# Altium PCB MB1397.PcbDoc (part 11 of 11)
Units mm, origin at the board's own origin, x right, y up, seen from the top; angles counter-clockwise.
Board outline 118.24 x 172.86 mm, 6 copper layers (Top Layer, L2_GND, L3_VCC, L4_SIG, L5_GND, Bottom Layer), stack 1.631 mm thick; 819 components, 632 nets, 2875 pads, 1523 vias.
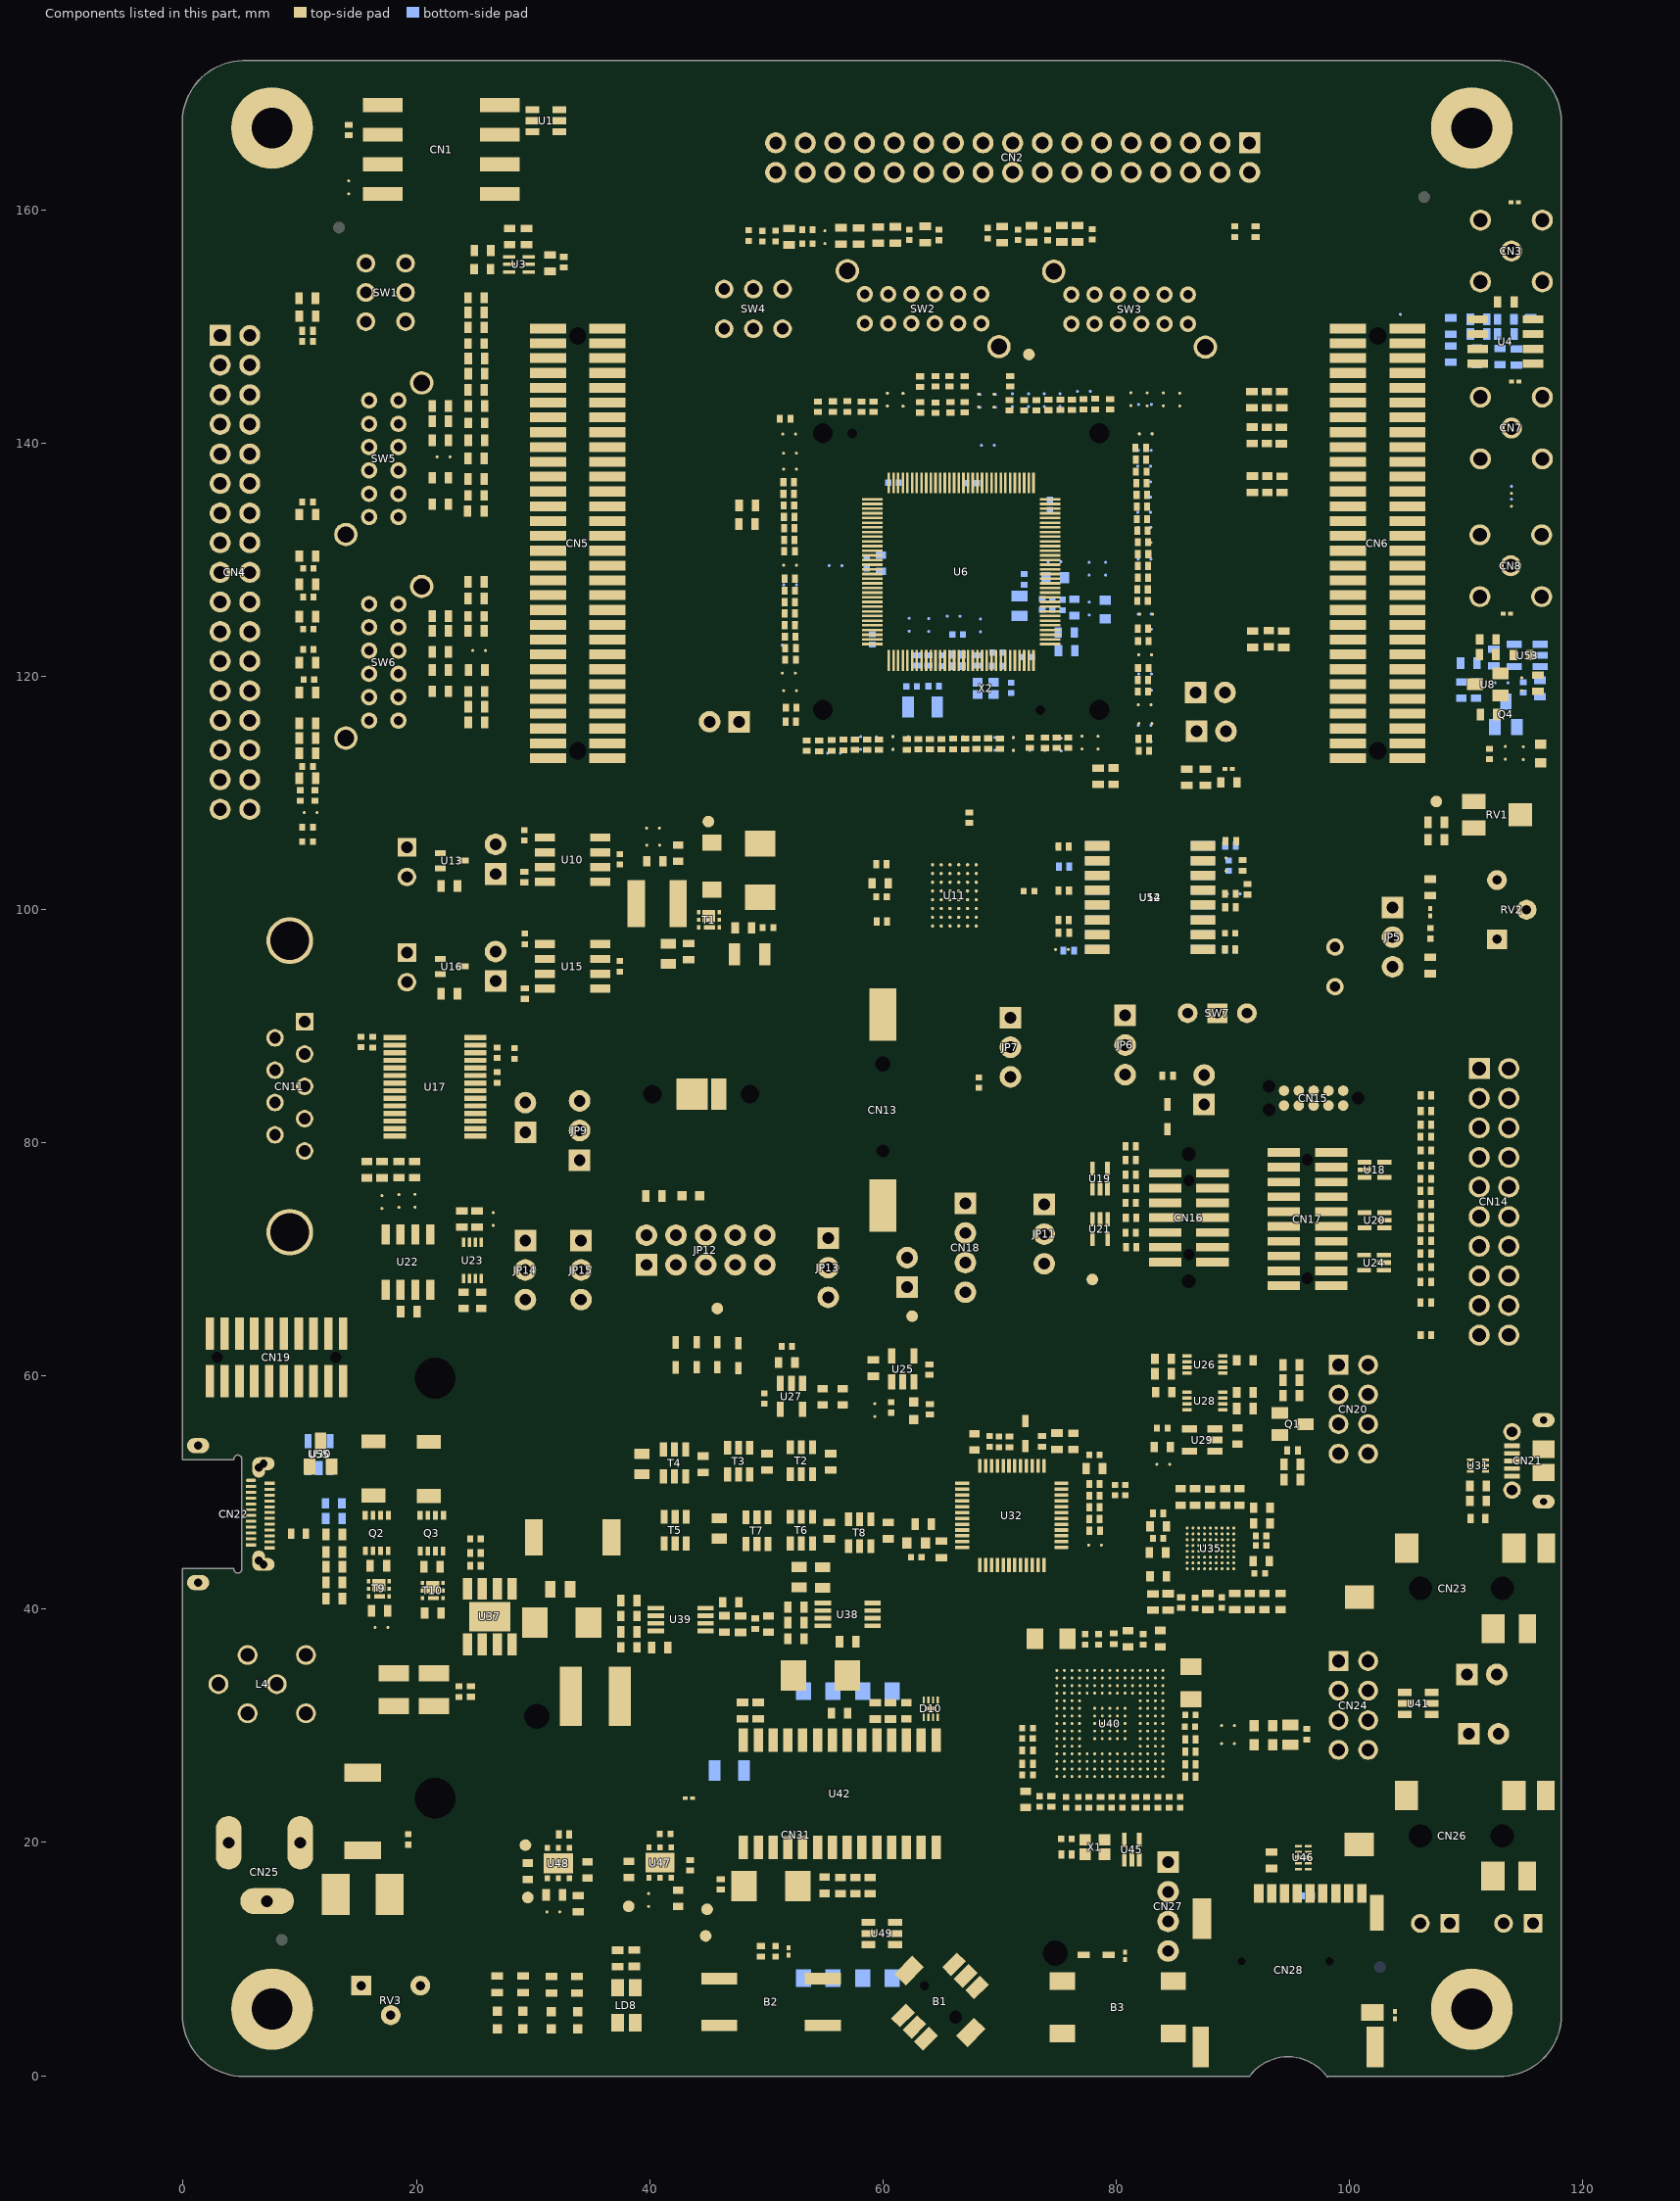
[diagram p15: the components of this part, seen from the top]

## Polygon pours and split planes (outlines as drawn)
no net on Top Overlay (solid): 103.025,168.605 ccw(c102.567,168.605) 102.567,169.063 ccw(c102.567,168.605) 102.109,168.605 ccw(c102.567,168.605) 102.567,168.147 ccw(c102.567,168.605) 103.025,168.605
no net on Top Overlay (solid): 102.707,164.287 ccw(c102.059,164.287) 102.059,164.935 ccw(c102.059,164.287) 101.411,164.287 ccw(c102.059,164.287) 102.059,163.64 ccw(c102.059,164.287) 102.707,164.287
no net on Top Overlay (solid): 99.392,168.605 99.392,169.24 99.646,169.24 99.646,168.605 99.392,168.605
no net on Top Overlay (solid): 100.154,167.208 100.154,166.7 101.678,166.7 101.678,167.208 100.154,167.208
no net on Top Overlay (solid): 99.519,163.716 99.773,163.716 99.773,164.16 99.519,164.16 99.519,163.716
no net on Top Overlay (solid): 103.025,168.605 ccw(c102.567,168.605) 102.567,169.063 ccw(c102.567,168.605) 102.109,168.605 ccw(c102.567,168.605) 102.567,168.147 ccw(c102.567,168.605) 103.025,168.605
no net on Top Overlay (solid): 102.707,164.287 ccw(c102.059,164.287) 102.059,164.935 ccw(c102.059,164.287) 101.411,164.287 ccw(c102.059,164.287) 102.059,163.64 ccw(c102.059,164.287) 102.707,164.287
no net on Top Overlay (solid): 99.392,168.605 99.392,169.24 99.646,169.24 99.646,168.605 99.392,168.605
no net on Top Overlay (solid): 100.154,167.208 100.154,166.7 101.678,166.7 101.678,167.208 100.154,167.208
no net on Top Overlay (solid): 99.519,163.716 99.773,163.716 99.773,164.16 99.519,164.16 99.519,163.716
no net on Top Overlay (solid): 457 vertices, not listed, extent 69.214,77.689 75.841,83.176
no net on Top Overlay (solid): 227 vertices, not listed, extent 72.022,78.87 74.874,81.995
no net on Top Overlay (solid): 457 vertices, not listed, extent 69.214,77.689 75.841,83.176
no net on Top Overlay (solid): 227 vertices, not listed, extent 72.022,78.87 74.874,81.995
GND on Top Layer "L4_SIG-No Net" (solid, pour order 261): 25 vertices, not listed, extent 23.467,36.703 32.004,49.2
GND_EXT_UNFILT on Top Layer "TOP-GND_EXT_UNFILT" (solid, pour order 215): 17 vertices, not listed, extent 8.862,20.368 19.756,32.433
NetLD5_2 on Top Layer "L4_SIG-No Net" (solid, pour order 256): 38.875,89.637 38.215,88.976 38.215,79.591 39.04,78.765 44.348,78.765 44.968,79.385 44.968,89.118 44.45,89.637
AGND on Top Layer "L4_SIG-No Net" (solid, pour order 264): 79.395,111.115 81.923,111.115 82.166,110.871 82.166,109.774 81.945,109.553 79.582,109.553 79.231,109.904 79.231,110.92 79.334,111.023
5V_USB_CHGR on Top Layer "TOP-5V_USB_CHGR" (solid, pour order 226): 26 vertices, not listed, extent 46.835,60.627 61.44,65.453
NetC63_2 on Top Layer "TOP-NETC77_1" (solid, pour order 232): 17 vertices, not listed, extent 41.374,58.989 51.534,63.421
5V_USB_PD on Top Layer "TOP-5V_USB_PD" (solid, pour order 219): 32.865,64.437 42.771,64.437 43.025,64.183 43.025,62.278 42.771,62.024 33.119,62.024 23.868,52.774 14.709,52.774 14.315,53.167 14.315,55.166 14.732,55.583 24.011,55.583 32.865,64.437
GND on Top Layer "TOP-GND 1" (solid, pour order 212): 52.036,59.492 51.915,59.613 51.915,60.582 51.915,61.727 51.915,62.128 51.915,62.944 51.915,63.167 52.169,63.421 53.312,63.421 53.566,63.167 53.566,60.819
NetC71_2 on Top Layer "Top Layer-NetC71_2" (solid, pour order 208): 21 vertices, not listed, extent 49,56.055 51.599,57.905
3V3_STLK on Top Layer "TOP-3V3_STLK" (solid, pour order 224): 17 vertices, not listed, extent 52.296,55.928 57.757,57.96
5V on Top Layer "TOP-5V 2" (solid, pour order 230): 618 vertices, not listed, extent 37.818,71.041 51.534,76.883
5V on Top Layer "TOP-5V 1" (solid, pour order 229): 53 vertices, not listed, extent 41.563,15.542 44.676,17.955
SH1_D on Top Layer "TOP-SH1_D" (solid, pour order 202): 25 vertices, not listed, extent 44.93,47.292 47.978,55.166
NetC151_2 on Top Layer "TOP-NETC34_2" (solid, pour order 209): 95 vertices, not listed, extent 27.912,13.129 31.468,17.32
NetC149_2 on Top Layer "TOP-NETC29_2" (solid, pour order 210): 156 vertices, not listed, extent 37.183,15.542 41.247,17.32
AMP_VDD on Top Layer "TOP-AMP_VDD" (solid, pour order 217): 30 vertices, not listed, extent 39.723,39.926 46.708,49.07
AMP_5V on Top Layer "TOP-AMP_5V" (solid, pour order 218): 18 vertices, not listed, extent 56.106,44.066 58.392,48.892
VIN_EXT_UNFILT on Top Layer "TOP-VIN_EXT_UNFILT" (solid, pour order 220): 28 vertices, not listed, extent 2.639,11.834 20.292,32.56
VIN_EXT_CONN on Top Layer "TOP-VIN_EXT_CONN" (solid, pour order 221): 17 vertices, not listed, extent 7.719,11.478 14.958,23.035
1V8_LDO on Top Layer "TOP-1V8_LDO" (solid, pour order 222): 89 vertices, not listed, extent 84.3,51.737 87.221,54.912
1V8 on Top Layer "TOP-1V8" (solid, pour order 223): 64 vertices, not listed, extent 82.141,50.34 83.919,53.134
5V_USB_CHGR on Top Layer "TOP-5V_USB_CHGR 1" (solid, pour order 227): 22 vertices, not listed, extent 111.224,46.784 112.875,51.483
VIN_EXT on Top Layer "TOP-VIN_EXT" (solid, pour order 235): 35 vertices, not listed, extent 4.036,33.195 26.132,39.164
GND on Top Layer "TOP-GND" (solid, pour order 211): 21 vertices, not listed, extent 47.662,94.104 51.661,102.791
3V3 on Top Layer "TOP-3V3" (solid, pour order 225): 77 vertices, not listed, extent 36.802,12.748 41.374,15.669
5V on Top Layer "TOP-5V" (solid, pour order 228): 48 vertices, not listed, extent 1.115,97.965 36.548,103.045
GND on Top Layer "TOP-GND 3" (solid, pour order 214): 15.847,29.258 15.466,29.639 15.466,32.052 15.847,32.433 16.655,32.433 19.51,32.433 20.511,32.433 22.939,32.433 23.32,32.814 24.077,32.814 24.892,32.814 25.654,32.814 25.654,30.81 24.102,29.258
GND on Top Layer "TOP-GND 2" (solid, pour order 213): 19 vertices, not listed, extent 16.863,39.291 19.022,41.247
SH0_D on Top Layer "TOP-SH0_D" (solid, pour order 203): 21 vertices, not listed, extent 38.326,50.086 42.517,54.912
T50_6 on Top Layer "TOP-T50_6" (solid, pour order 200): 49 vertices, not listed, extent 44.93,40.307 56.106,49.197
SH2_D on Top Layer "TOP-SH2_D" (solid, pour order 201): 22 vertices, not listed, extent 51.026,43.228 53.947,49.197
NetL5_1 on Top Layer "L4_SIG-No Net" (solid, pour order 260): 17 vertices, not listed, extent 26.67,29.134 34.722,35.692
CAL_D on Top Layer "TOP-CAL_D" (solid, pour order 216): 65 vertices, not listed, extent 48.232,46.657 54.709,55.547
NetR249_1 on Top Layer "TOP-NETR324_1" (solid, pour order 204): 23 vertices, not listed, extent 19.784,41.406 22.959,44.123
NetR246_1 on Top Layer "TOP-NETR318_1" (solid, remove dead copper, pour order 205): 23 vertices, not listed, extent 13.307,39.799 17.922,45.514
NetC41_1 on Top Layer "TOP-NETC22_2" (solid, pour order 231): 40.993,103.172 40.739,103.426 40.739,103.576 41.59,103.576 41.59,104.696 43.406,104.696 43.787,105.077 43.787,107.744 44.676,108.633 51.153,108.633 51.415,108.372 51.415,104.235 51.114,103.934 44.422,103.934 43.66,103.172
NetD1_1 on Top Layer "Top Layer-NetD1_1" (solid, pour order 233): 41.501,97.965 41.247,98.219 41.247,102.791 43.818,102.791 43.945,102.918 46.454,102.918 46.611,102.762 46.611,99.519 46.611,99.265 46.2,98.854 43.914,98.854 43.66,98.6 43.66,98.219 43.406,97.965
NetR172_1 on Top Layer "TOP-NETR48_1" (solid, pour order 234): 30 vertices, not listed, extent 44.676,94.513 48.232,99.362
VBUS on Top Layer "TOP-VBUS" (solid, remove dead copper, pour order 199): 32 vertices, not listed, extent 10.97,39.418 18.26,50.975
NetQ2_1 on Top Layer "TOP-NETQ2_1 1" (solid, pour order 207): 14.958,43.101 14.755,43.304 14.755,45.184 14.958,45.387 17.117,45.387 17.117,44.625 16.961,44.469 15.591,44.457 15.591,43.101
NetQ2_1 on Top Layer "TOP-NETQ2_1" (solid, pour order 206): 18.982,44.069 18.885,44.166 18.885,45.263 19.012,45.39 21.806,45.39 21.806,44.628 21.679,44.501 21.328,44.501 19.743,44.501 19.312,44.069
5V_EXT on Top Layer "L4_SIG-No Net" (solid, pour order 262): 40 vertices, not listed, extent 19.276,29.261 39.219,54.509
NetLD5_2 on Bottom Layer "Bottom Layer-NetLD5_2" (solid, pour order 257): 38.875,89.637 44.45,89.637 44.968,89.118 44.968,79.385 44.348,78.765 39.04,78.765 38.215,79.591 38.215,88.964 38.532,89.281
VDD on Bottom Layer "BOTTOM-VDD" (solid, pour order 236): 149 vertices, not listed, extent 83.03,60.754 106.906,64.564
VDD1 on Bottom Layer "BOTTOM-VDD1" (solid, pour order 237): 136 vertices, not listed, extent 62.329,42.466 74.775,53.642
NetQ2_1 on Bottom Layer "BOTTOM-NETQ2_1" (solid, pour order 238): 19.657,45.26 19.657,44.244 19.53,44.117 16.482,44.117 16.101,43.736 16.101,43.228 15.974,43.101 14.958,43.101 14.755,43.304 14.755,45.184 14.958,45.387 19.53,45.387 19.657,45.26
GND_EXT_UNFILT on Bottom Layer "BOTTOM-GND_EXT_UNFILT" (solid, pour order 239): 26 vertices, not listed, extent 0.734,13.002 17.879,32.433
AGND on L4_SIG "L4_SIG-No Net" (solid, pour order 265): 21 vertices, not listed, extent 76.022,109.964 82.549,123.977
VDD1 on L4_SIG "L4_SIG-VDD1" (solid, pour order 240): 185 vertices, not listed, extent 51.407,41.323 66.012,67.739
3V3 on L4_SIG "L4_SIG-3V3" (solid, pour order 243): 442 vertices, not listed, extent 36.675,8.303 97.254,17.447
5V_EXT on L4_SIG "L4_SIG-No Net" (solid, pour order 263): 30.071,52.603 33.779,52.603 48.74,67.564 48.74,70.423 48.28,70.884 46.419,70.884 46.025,70.49 46.025,68.044 32.593,54.612 29.545,54.612 29.21,54.277 29.21,52.924 29.531,52.603 29.591,52.59
VIN_EXT_CONN on L4_SIG "L4_SIG-VIN_EXT_CONN" (solid, pour order 242): 14.78,11.478 10.792,11.478 10.361,11.91 10.361,15.847 7.719,18.489 7.719,22.019 8.735,23.035 10.386,23.035 12.545,20.876 12.545,18.336 13.18,17.701 14.704,17.701 14.958,17.447 14.958,11.656 14.78,11.478
VIN_EXT_UNFILT on L4_SIG "L4_SIG-VIN_EXT_UNFILT" (solid, pour order 241): 23 vertices, not listed, extent 2.639,11.834 20.292,32.56
VIN_EXT on L4_SIG "L4_SIG-VIN_EXT" (solid, pour order 244): 32 vertices, not listed, extent 4.036,33.195 23.391,39.164
1V8 on L4_SIG "L4_SIG-No Net" (solid, pour order 255): 19 vertices, not listed, extent 82.296,40.856 93.525,53.008
5V on L3_VCC "L3_VCC-5V 1" (solid, remove dead copper, pour order 253): 72 vertices, not listed, extent 0.445,100.633 117.666,172.274
VBUS on L3_VCC "L3_VCC-VBUS" (solid, remove dead copper, pour order 248): 0.445,39.419 0.445,65.913 11.227,65.913 13.435,63.705 13.435,40.031 12.822,39.419
5V on L3_VCC "L3_VCC-5V" (solid, remove dead copper, pour order 252): 42 vertices, not listed, extent 33.501,8.431 92.429,114.095
VDD on L3_VCC "L3_VCC-VDD" (solid, remove dead copper, pour order 246): 58 vertices, not listed, extent 42.645,27.735 94.207,78.535
3V3_STLK on L3_VCC "L3_VCC-3V3_STLK" (solid, pour order 249): 22 vertices, not listed, extent 54.583,17.018 86.587,61.009
3V3 on L3_VCC "L3_VCC-3V3" (solid, pour order 250): 48 vertices, not listed, extent 72.871,11.733 103.859,86.663
3V3 on L3_VCC "L3_VCC-3V3" (solid, remove dead copper, pour order 251): 53 vertices, not listed, extent 0.445,0.446 111.479,164.387
VDD on L3_VCC "L3_VCC-VDD" (solid, pour order 245): 117 vertices, not listed, extent 20.801,0.446 117.666,157.275
VDD_MCU on L3_VCC "L3_VCC-VDD_MCU" (solid, remove dead copper, pour order 247): 25 vertices, not listed, extent 52.297,67.867 86.587,138.162
AGND on L2_GND "L2_GND-AGND" (solid, pour order 259): 37 vertices, not listed, extent 76.68,107.076 117.665,161.107
GND_EXT_UNFILT on L2_GND "L2_GND-GND" (solid, remove dead copper, pour order 267): 25 vertices, not listed, extent 0.445,12.967 17.819,32.346
GND on L2_GND "L2_GND-GND" (solid, remove dead copper, pour order 266): 132 vertices, not listed, extent 0.445,0.445 117.666,172.273
no net on Top Solder "L4_SIG-No Net" (solid): 38.875,89.637 44.45,89.637 44.968,89.118 44.968,79.385 44.348,78.765 39.04,78.765 38.215,79.591 38.215,88.976
GND_EXT_UNFILT on L5_GND "L5_GND-GND" (solid, remove dead copper, pour order 268): 23 vertices, not listed, extent 0.444,13.005 17.836,32.346
AGND on L5_GND "L5_GND-AGND" (solid, pour order 254): 108.92,114.475 108.92,135.237 108.097,136.06 108.097,158.852 110.353,161.107 117.665,161.107 117.665,113.713 109.682,113.713 108.92,114.475
GND on L5_GND "L5_GND-GND" (solid, remove dead copper, pour order 269): 99 vertices, not listed, extent 0.452,0.42 117.673,172.249
no net on Bottom Solder "L4_SIG-No Net" (solid): 38.875,89.637 44.45,89.637 44.968,89.118 44.968,79.385 44.348,78.765 39.04,78.765 38.215,79.591 38.215,88.976

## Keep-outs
L2_GND:
  lines w0.254: 90.721,0.056 cw(c94.742,-2.515) 98.779,0.03
L3_VCC:
  lines w0.254: 90.721,0.056 cw(c94.742,-2.515) 98.779,0.03
L5_GND:
  lines w0.254: 90.721,0.056 cw(c94.742,-2.515) 98.779,0.03
Bottom Layer:
  circle w0.025: c54.843,117.106 r2.505
  circle w0.025: c78.563,117.106 r2.505
  circle w0.025: c54.843,140.831 r2.505
Keep-Out Layer:
  lines w0.127: 118.11,5.156 118.11,5.156
Multi-Layer:
  circle w0.025: c57.383,140.826 r0.705
  circle w0.025: c54.843,117.106 r1.105
  circle w0.025: c54.843,140.826 r1.105
  circle w0.025: c78.563,140.826 r1.105
  circle w0.025: c78.563,117.106 r1.105
  circle w0.025: c73.483,117.106 r0.705

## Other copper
Top Layer:
  rectangle net GND: 27.324,38.1 29.25,40.12
  rectangle net NetR249_1: 20.222,41.456 22.614,42.517
  rectangle net NetC63_2: 50.458,59.182 51.317,59.776
  rectangle net NetR246_1: 15.419,41.581 17.922,42.545
  rectangle net NetQ2_1: 19.53,44.501 21.776,45.387
  rectangle net AMP_VDD: 41.011,47.802 41.467,48.943
  rectangle net AMP_VDD: 41.958,45.63 42.364,48.901
  rectangle net SH0_D: 40.505,53.414 42.257,53.911
  rectangle net SH0_D: 40.601,51.151 42.279,51.664
  rectangle net GND: 23.789,38.1 28.789,40.64
  text "1" at 57.462,-24.867 h1.91
  text "1" at 57.462,-24.867 h1.91
  text "PRIMARY SIDE" at 44.762,-28.677 h1.52
  text "PRIMARY SIDE" at 44.762,-28.677 h1.52
Bottom Layer:
  text "6" at 56.192,-24.867 h1.91
  text "6" at 56.192,-24.867 h1.91
  text "SECONDARY SIDE" at 44.762,-28.677 h1.52
Multi-Layer:
  text "FAB DARWING & DRILL LEGEND" at 44.762,-28.677 h1.52

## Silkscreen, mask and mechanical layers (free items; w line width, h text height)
Top Overlay:
  drawing of 2954 lines, arcs and shapes, not listed
  text "EXT I2C" at 21.189,170.942 h0.76
  text "MB1397B" at 92.606,170.231 h0.89
  text "STM32G474E-EVAL" at 71.45,170.155 h1.52
  text "MC1" at 66.761,169.545 h0.76
  text "AIN" at 109.67,159.133 h0.76 r90
  text "MC2" at 4.699,154.912 h0.76
  text "COMP_OUT" at 72.898,149.885 h0.76 r90
  text "PC8" at 26.924,149.482 h0.76
  text "PC7" at 95.377,149.426 h0.76
  text "PC6" at 106.934,149.428 h0.76
  text "PA8" at 38.687,149.352 h0.76
  text "PA11" at 26.924,148.202 h0.76
  text "PD15" at 95.377,148.158 h0.76
  text "PD14" at 106.934,148.158 h0.76
  text "PA10" at 38.707,148.067 h0.76
  text "PD12" at 106.934,146.962 h0.76
  text "PD13" at 95.377,146.939 h0.76
  text "PA12" at 26.886,146.914 h0.76
  text "PA13" at 38.707,146.914 h0.76
  text "PD10" at 106.934,145.745 h0.76
  text "PA9" at 38.707,145.669 h0.76
  text "PD11" at 95.377,145.641 h0.76
  text "PF6" at 26.886,145.545 h0.76
  text "GND" at 38.661,144.399 h0.76
  text "PD9" at 95.377,144.399 h0.76
  text "GND" at 106.934,144.385 h0.76
  text "PA14" at 26.856,144.1 h0.76
  text "PB14" at 95.377,143.129 h0.76
  text "PA15" at 38.687,143.002 h0.76
  text "PD8" at 106.934,143.002 h0.76
  text "PC9" at 26.856,142.878 h0.76
  text "PB13" at 95.377,141.732 h0.76
  text "PC10" at 26.856,141.712 h0.76
  text "PC12" at 38.687,141.712 h0.76
  text "PB15" at 106.934,141.67 h0.76
  text "PG5" at 38.674,140.589 h0.76
  text "PB11" at 95.377,140.545 h0.76
  text "PB12" at 106.934,140.538 h0.76
  text "PC11" at 26.856,140.483 h0.76
  text "PG2" at 38.687,139.362 h0.76
  text "PE15" at 106.934,139.342 h0.76
  text "PG4" at 26.856,139.219 h0.76
  text "PB10" at 95.377,139.205 h0.76
  text "PE13" at 106.934,138.125 h0.76
  text "PG3" at 26.886,138.05 h0.76
  text "GND" at 38.674,138.05 h0.76
  text "PE14" at 95.377,137.922 h0.76
  text "PG0" at 38.725,136.779 h0.76
  text "PE12" at 95.377,136.765 h0.76
  text "PE11" at 106.934,136.765 h0.76
  text "PG1" at 26.886,136.652 h0.76
  text "AIN+" at 115.189,136.522 h0.76
  text "PG6" at 38.725,135.581 h0.76
  text "PE9" at 106.934,135.487 h0.76
  text "PE10" at 95.377,135.441 h0.76
  text "PG7" at 26.886,135.255 h0.76
  text "PG9" at 38.753,134.237 h0.76
  text "PE8" at 95.377,134.227 h0.76
  text "PG8" at 26.924,134.112 h0.76
  text "PF15" at 106.991,133.982 h0.76
  text "AIN-" at 115.189,133.601 h0.76
  text "PD1" at 38.834,132.969 h0.76
  text "PE7" at 95.377,132.969 h0.76
  text "PD0" at 26.924,132.89 h0.76
  text "PF14" at 106.991,132.712 h0.76
  text "PF13" at 95.377,131.811 h0.76
  text "PD2" at 26.924,131.699 h0.76
  text "NRST" at 38.834,131.62 h0.76
  text "PF12" at 106.991,131.516 h0.76
  text "PF0" at 26.924,130.429 h0.76
  text "PF11" at 95.377,130.429 h0.76
  text "PF1" at 38.902,130.302 h0.76
  text "PB2" at 106.991,130.299 h0.76
  text "PB1" at 95.377,129.286 h0.76
  text "PD3" at 38.88,129.189 h0.76
  text "PD4" at 26.924,129.053 h0.76
  text "PC5" at 106.991,128.939 h0.76
  text "PB0" at 95.377,127.937 h0.76
  text "PC15" at 38.902,127.919 h0.76
  text "PC14" at 26.416,127.81 h0.76
  text "PC4" at 107.003,127.702 h0.76
  text "PD5" at 38.902,126.619 h0.76
  text "PD6" at 26.856,126.513 h0.76
  text "PA7" at 95.377,126.489 h0.76
  text "PA6" at 107.003,126.489 h0.76
  text "PD7" at 38.902,125.349 h0.76
  text "GND" at 26.856,125.312 h0.76
  text "GND" at 95.377,125.219 h0.76
  text "PA5" at 107.003,125.222 h0.76
  text "PB4" at 38.902,124.126 h0.76
  text "PB3" at 26.856,124.082 h0.76
  text "PA4" at 95.377,124.051 h0.76
  text "PA3" at 107.003,124.003 h0.76
  text "PB5" at 26.856,122.812 h0.76
  text "PB6" at 38.902,122.784 h0.76
  text "PA2" at 95.377,122.735 h0.76
  text "PA1" at 107.003,122.743 h0.76
  text "PA0" at 95.377,121.446 h0.76
  text "PF2" at 107.003,121.412 h0.76
  text "PE5" at 26.924,121.397 h0.76
  text "PC0" at 38.902,121.397 h0.76
  text "PC3" at 95.377,120.169 h0.76
  text "VDD" at 38.88,120.142 h0.76
  text "VDD" at 107.003,120.142 h0.76
  text "PB7" at 26.856,120.102 h0.76
  text "PE2" at 38.979,119 h0.76
  text "5V_D" at 26.797,118.872 h0.76
  text "PC2" at 106.934,118.872 h0.76
  text "5V_D" at 95.377,118.793 h0.76
  text "DAC2" at 93.116,117.789 h0.76 r90
  text "PB8" at 38.958,117.759 h0.76
  text "PC1" at 106.934,117.676 h0.76
  text "PB9" at 26.924,117.602 h0.76
  text "PF10" at 95.377,117.602 h0.76
  text "PE3" at 38.979,116.474 h0.76
  text "PE1" at 26.924,116.459 h0.76
  text "PF5" at 95.377,116.441 h0.76
  text "PF7" at 106.934,116.441 h0.76
  text "PE0" at 26.924,115.237 h0.76
  text "PF9" at 95.377,115.189 h0.76
  text "PF8" at 106.934,115.189 h0.76
  text "PE4" at 38.958,115.092 h0.76
  text "DAC" at 93.218,114.259 h0.76 r90
  text "PC13" at 26.856,113.985 h0.76
  text "PE6" at 38.958,113.909 h0.76
  text "PF4" at 95.377,113.919 h0.76
  text "PF3" at 106.934,113.919 h0.76
  text "CAN1_RX" at 44.094,113.473 h0.76
  text "5V" at 38.979,112.796 h0.76
  text "GND" at 26.924,112.697 h0.76
  text "GND" at 95.377,112.587 h0.76
  text "5V" at 106.807,112.57 h0.76
  text "OPA_OUT" at 103.175,110.781 h0.76
  text "5V" at 44.488,109.852 h0.76
  text "CAN2" at 17.366,101.653 h0.76 r90
  text "USART" at 3.937,100.95 h0.76
  text "POT" at 102.182,99.503 h0.76 r90
  text "LDR" at 102.083,93.842 h0.76 r90
  text "1 <----> 0" at 84.785,92.862 h0.76
  text "CAN1" at 17.172,92.456 h0.76 r90
  text "JTAG" at 113.411,91.945 h0.76
  text "0=Flash" at 94.056,91.745 h0.76
  text "1=Sys Mem" at 94.107,90.703 h0.76
  text "HB_LED" at 46.662,90.076 h0.76
  text "VDD" at 73.495,89.527 h0.76 r90
  text "BOOT0" at 94.437,89.282 h0.76
  text "VDD_MCU" at 78.867,88.646 h0.76 r90
  text "TAG" at 97.33,87.63 h0.76
  text "VCP_RX" at 28.296,85.522 h0.76
  text "3V3" at 78.913,84.833 h0.76 r90
  text "BAT" at 73.492,84.574 h0.76 r90
  text "BL_BOOT0" at 90.043,82.169 h0.76 r90
  text "RS485" at 36.636,82.014 h0.76 r90
  text "RS232" at 36.548,76.659 h0.76 r90
  text "5V PWR" at 48.006,75.095 h0.76
  text "3V3" at 71.89,73.779 h0.76 r90
  text "U5V" at 41.042,73.635 h0.76
  text "D5V" at 43.739,73.635 h0.76
  text "E5V" at 46.372,73.627 h0.76
  text "CHGR" at 48.912,73.627 h0.76
  text "STLK" at 38.049,73.609 h0.76
  text "IDD" at 57.744,71.01 h0.76 r90
  text "GND" at 31.743,70.739 h0.76 r90
  text "GND" at 36.662,70.681 h0.76 r90
  text "ADJ" at 71.945,68.389 h0.76 r90
  text "5V Source" at 38.834,66.929 h0.76
  text "BL_RESET" at 64.75,66.461 h0.76 r90
  text "TYPE-C SIG" at 6.731,66.167 h0.76
  text "STDC14" at 86.563,65.913 h0.76
  text "TRACE" at 96.393,65.786 h0.76
  text "5V_EXT=5.2V" at 37.465,65.405 h0.76
  text "DBCC1" at 36.703,65.278 h0.76 r90
  text "DBCC2" at 31.877,65.238 h0.76 r90
  text "1V8" at 76.782,65.199 h0.76
  text "MFX" at 68.146,64.64 h0.76
  text "BYPASS" at 57.757,64.465 h0.76 r90
  text "STLINK V3E USB HS" at 107.315,57.15 h0.76
  text "TYPE-C" at 2.921,53.848 h0.76
  text "CURR OVER" at 64.421,49.911 h0.76 r90
  text "LCD_SIG" at 97.917,49.174 h0.76
  text "Audio_In" at 104.267,36.474 h0.76
  text "-" at 112.304,36.093 h0.76
  text "+" at 109.736,36.068 h0.76
  text "-" at 112.431,30.988 h0.76
  text "+" at 109.863,30.963 h0.76
  text "Audio_Out" at 106.299,25.796 h0.76
  text "+" at 0.646,25.555 h0.76
  text "-" at 2.628,25.541 h0.76
  text "PSU" at 5.565,25.121 h0.76
  text "LCD_PWR" at 97.815,24.232 h0.76
  text "PG" at 27.889,22.073 h0.76
  text "ST-LINK" at 86.535,17.018 h0.76
  text "JTMS" at 104.14,14.605 h0.76
  text "JTCK" at 107.95,14.605 h0.76
  text "ADJ" at 26.54,14.402 h0.76
  text "AUX2" at 46.025,12.04 h0.76
  text "3V3" at 37.418,11.961 h0.76
  text "NRST" at 114.681,10.541 h0.76
  text "AUX1" at 41.648,10.185 h0.76
  text "uSD" at 104.775,8.382 h0.76 r90
  text "COM" at 36.83,1.778 h0.76
  text "USER" at 49.53,0.762 h0.89
  text "Joystick" at 62.908,0.6 h0.89
  text "RESET" at 77.297,0.508 h0.89
  text "SILKSCREEN, (PRIMARY)" at 44.762,-28.677 h1.52
Bottom Overlay:
  lines w0.127: 67.31,38.083 73.894,38.083 ; 67.31,38.133 67.31,39.482 73.69,39.482 73.911,39.261 73.911,38.101 ; 67.539,36.524 67.539,36.573 ; 70.646,124.774 70.646,127.553 70.646,129.043 70.646,129.54 62.992,129.54 62.992,133.147 69.615,133.147 71.133,133.147 71.133,127.693 71.19,127.635 71.478,127.635 ; 71.553,124.488 72.765,124.488 72.855,124.578 76.879,124.578 77.379,124.079 80.236,124.079 80.236,124.536 ; 72.898,127.381 75.281,127.381 ; 74.122,36.524 74.14,36.542 ; 76.073,127.381 78.565,127.381 ; 79.591,127.381 80.165,127.381 80.165,125.499 ; 116.332,145.479 116.332,152.176 109.982,152.176 109.982,158.877 101.346,158.877 101.346,152.342 107.627,152.342 107.627,145.542 116.332,145.542 ; 33.122,169.112 34.823,169.112 41.407,169.112 41.425,169.13 41.425,170.663 33.122,170.663 33.122,169.112 ; 46.203,65.507 46.204,65.505 46.965,65.505 53.548,65.505 53.566,65.523 53.566,66.683 53.345,66.904 46.203,66.904 46.203,66.317 46.203,65.507
  text "product sticker" at 41.072,169.619 h0.76
  text "board sticker" at 53.21,65.837 h0.76
  text "Smart Card" at 73.556,38.415 h0.76
  text "SILKSCREEN, (SECONDARY)" at 75.115,-28.804 h1.52
Top Paste:
  text "SOLDER PASTE (PRIMARY)" at 44.762,-28.677 h1.52
  text "SOLDER PASTE (PRIMARY)" at 44.762,-28.677 h1.52
Bottom Paste:
  text "SOLDER PASTE (SECONDARY)" at 44.762,-28.677 h1.52
  text "SOLDER PASTE (SECONDARY)" at 44.762,-28.677 h1.52
Top Solder:
  text "SOLDER MASK (PRIMARY)" at 44.762,-28.677 h1.52
  text "SOLDER MASK (PRIMARY)" at 44.762,-28.677 h1.52
Bottom Solder:
  text "SOLDER MASK (SECONDARY)" at 44.762,-28.677 h1.52
  text "SOLDER MASK (SECONDARY)" at 44.762,-28.677 h1.52
M1-Board Shape:
  lines w0.127: 0,43.434 0,5.258 ccw(c5.207,5.207) 5.156,0 91.38,0 cw(c94.742,-2.502) 98.116,-0.016 ; 0,52.884 0,167.564 cw(c5.207,167.513) 5.258,172.72 ; 5.105,172.72 40.783,172.72 112.954,172.72 cw(c112.903,167.513) 118.11,167.462 118.11,24.765 118.11,5.156 cw(c112.903,5.207) 112.852,0 98.116,0
M8-Bottom Info:
  text "4" at 38.644,-6.807 h1.91
  text "4" at 38.644,-6.807 h1.91
  text "LAYER 4 (INTERNAL SIGNAL)" at 25.944,-10.617 h1.52
  text "LAYER 4 (INTERNAL SIGNAL)" at 25.944,-10.617 h1.52
M12-Top 3D Body:
  text "5" at 38.644,-6.807 h1.91
  text "5" at 38.644,-6.807 h1.91
  text "LAYER 5 (GND PLANE)" at 25.944,-10.617 h1.52
  text "LAYER 5 (GND PLANE)" at 25.944,-10.617 h1.52
M13-Bottom 3D Body:
  text "3" at 38.644,-6.807 h1.91
  text "3" at 38.644,-6.807 h1.91
  text "LAYER 3 (VTT PLANE)" at 25.944,-10.617 h1.52
  text "LAYER 3 (VTT PLANE)" at 25.944,-10.617 h1.52
M14-Top Assembly:
  text "2" at 38.644,-6.807 h1.91
  text "2" at 38.644,-6.807 h1.91
  text "LAYER 2 (GND PLANE)" at 25.944,-10.617 h1.52
  text "LAYER 2 (GND PLANE)" at 25.944,-10.617 h1.52
Drill Drawing:
  drawing of 25954 lines, arcs and shapes, not listed
  text "6" at -9.855,302.895 h3.3
  text "6" at -9.855,302.895 h3.3
  text "5" at 79.045,302.895 h3.3
  text "5" at 79.045,302.895 h3.3
  text "4" at 167.945,302.895 h3.3
  text "4" at 167.945,302.895 h3.3
  text "3" at 256.845,302.895 h3.3
  text "3" at 256.845,302.895 h3.3
  text "2" at 345.745,302.895 h3.3
  text "2" at 345.745,302.895 h3.3
  text "1" at 434.645,302.895 h3.3
  text "1" at 434.645,302.895 h3.3
  text "REVISIONS" at 402.59,296.266 h2.29
  text "DESCRIPTION" at 384.708,290.5 h1.91
  text "DATA" at 443.535,290.5 h1.91
  text "APPROVED" at 459.105,290.347 h1.91
  text "REV" at 374.32,290.093 h1.91
  text "1.0" at 374.117,285.42 h1.91
  text "***" at 460.883,285.217 h1.91
  text "2008-**-**" at 439.522,285.064 h1.91
  text "EDITION ORIGINALE" at 384.505,285.013 h1.91
  text "D" at -60.655,244.475 h3.3
  text "D" at -60.655,244.475 h3.3
  text "D" at 480.365,244.475 h3.3
  text "D" at 480.365,244.475 h3.3
  text "4" at 302.565,235.128 h1.91
  text "4" at 302.565,235.128 h1.91
  text "LAYER STUCK-UP" at 307.645,235.128 h1.91
  text "LAYER STUCK-UP" at 307.645,235.128 h1.91
  text "5" at -14.224,231.496 h2.54
  text "5" at -14.224,231.496 h2.54
  text "IMPEDANCE TABLE" at -6.35,230.988 h2.54
  text "IMPEDANCE TABLE" at -6.35,230.988 h2.54
  text "SOLDERMASK & SILKSCREEN" at 352.349,229.032 h1.52
  text "SOLDERMASK & SILKSCREEN" at 352.349,229.032 h1.52
  text "TOP     (0.5 oz cu+planted)" at 352.349,225.984 h1.52
  text "TOP     (0.5 oz cu+planted)" at 352.349,225.984 h1.52
  text "LAYER" at -8.255,223.52 h1.91
  text "LAYER" at -8.255,223.52 h1.91
  text "TOLERANCE" at 86.995,223.52 h1.91
  text "TOLERANCE" at 86.995,223.52 h1.91
  text "TRACE" at 10.795,223.266 h1.91
  text "TRACE" at 10.795,223.266 h1.91
  text "SPACEING" at 24.765,223.266 h1.91
  text "SPACEING" at 24.765,223.266 h1.91
  text "IMPEDANCE" at 43.815,223.266 h1.91
  text "IMPEDANCE" at 43.815,223.266 h1.91
  text "IMPEDANCE" at 66.675,223.266 h1.91
  text "IMPEDANCE" at 66.675,223.266 h1.91
  text "PREPREG  3.9 mil" at 318.821,221.793 h1.52
  text "PREPREG  3.9 mil" at 318.821,221.793 h1.52
  text "(mil)" at 12.065,220.98 h1.27
  text "(mil)" at 12.065,220.98 h1.27
  text "(Single end)" at 45.085,220.98 h1.27
  text "(Single end)" at 45.085,220.98 h1.27
  text "(mil)" at 27.305,220.726 h1.27
  text "(mil)" at 27.305,220.726 h1.27
  text "(Differential)" at 66.675,220.726 h1.27
  text "(Differential)" at 66.675,220.726 h1.27
  text "LAYER 2 (1 oz)" at 352.349,218.364 h1.52
  text "LAYER 2 (1 oz)" at 352.349,218.364 h1.52
  text "1,6" at -8.382,217.272 h1.91
  text "1,6" at -8.382,217.272 h1.91
  text "5.0" at 11.938,217.018 h1.91
  text "5.0" at 11.938,217.018 h1.91
  text "CORE     4  mil" at 318.821,215.824 h1.52
  text "CORE     4  mil" at 318.821,215.824 h1.52
  text "N/A" at 28.575,215.646 h1.91
  text "N/A" at 28.575,215.646 h1.91
  text "55 OHM" at 45.085,215.392 h1.91
  text "55 OHM" at 45.085,215.392 h1.91
  text "N/A" at 70.485,215.392 h1.91
  text "N/A" at 70.485,215.392 h1.91
  text "+/-10%" at 89.535,215.392 h1.91
  text "+/-10%" at 89.535,215.392 h1.91
  text "4.0" at 11.684,213.97 h1.91
  text "4.0" at 11.684,213.97 h1.91
  text "4" at -8.382,213.716 h1.91
  text "4" at -8.382,213.716 h1.91
  text "LAYER 3 (1 oz)" at 352.349,213.284 h1.52
  text "LAYER 3 (1 oz)" at 352.349,213.284 h1.52
  text "63 mil" at 296.672,211.442 h1.91
  text "63 mil" at 296.672,211.442 h1.91
  text "1,6" at -8.509,210.541 h1.91
  text "6.1" at 11.557,210.541 h1.91
  text "8.9" at 28.067,210.541 h1.91
  text "N/A" at 47.752,209.398 h1.91
  text "90 OHM" at 68.326,209.144 h1.91
  text "PREPREG  ** mil" at 318.821,209.093 h1.52
  text "PREPREG  ** mil" at 318.821,209.093 h1.52
  text "+/-10%" at 89.535,209.042 h1.91
  text "+/-10%" at 89.535,209.042 h1.91
  text "+/-10%" at 297.739,208.712 h1.27
  text "+/-10%" at 297.739,208.712 h1.27
  text "4" at -8.509,207.747 h1.91
  text "5.1" at 11.557,207.747 h1.91
  text "9.9" at 28.067,207.747 h1.91
  text "LAYER 4 (1 oz)" at 352.349,205.664 h1.52
  text "LAYER 4 (1 oz)" at 352.349,205.664 h1.52
  text "CORE     4  mil" at 318.821,203.124 h1.52
  text "CORE     4  mil" at 318.821,203.124 h1.52
  text "90 OHM" at 68.174,202.895 h1.91
  text "+/-10%" at 89.687,202.844 h1.91
  text "N/A" at 47.879,202.311 h1.91
  text "LAYER 5 (1 oz)" at 352.349,200.584 h1.52
  text "LAYER 5 (1 oz)" at 352.349,200.584 h1.52
  text "PREPREG  3.9 mil" at 318.821,196.393 h1.52
  text "PREPREG  3.9 mil" at 318.821,196.393 h1.52
  text "BOTTOM  (0.5 oz cu+planted)" at 352.349,192.964 h1.52
  text "BOTTOM  (0.5 oz cu+planted)" at 352.349,192.964 h1.52
  text "SOLDERMASK & SILKSCREEN" at 352.349,189.916 h1.52
  text "SOLDERMASK & SILKSCREEN" at 352.349,189.916 h1.52
  text "6 LAYER STACKING" at 317.297,185.344 h1.91
  text "6 LAYER STACKING" at 317.297,185.344 h1.91
  text "C" at -60.655,145.415 h3.3
  text "C" at -60.655,145.415 h3.3
  text "C" at 480.365,145.415 h3.3
  text "C" at 480.365,145.415 h3.3
  text "PCB SPECIFICATIONS:" at 302.463,138.125 h2.16
  text "PCB SPECIFICATIONS:" at 302.463,138.125 h2.16
  text "A. MATERIAL;" at 302.463,133.045 h2.16
  text "A. MATERIAL;" at 302.463,133.045 h2.16
  text "FR-4," at 346.913,133.045 h2.16
  text "FR-4," at 346.913,133.045 h2.16
  text "TG-170" at 371.043,133.045 h2.16
  text "TG-170" at 371.043,133.045 h2.16
  text "TG-150" at 390.093,133.045 h2.16
  text "TG-150" at 390.093,133.045 h2.16
  text "TG-140" at 411.683,133.045 h2.16
  text "TG-140" at 411.683,133.045 h2.16
  text "B. MATERIAL FAMILY;" at 302.463,127.965 h2.16
  text "B. MATERIAL FAMILY;" at 302.463,127.965 h2.16
  text "N/A." at 346.913,127.965 h2.16
  text "N/A." at 346.913,127.965 h2.16
  text "C. SOLDERMASK COLOR;" at 302.463,122.885 h2.16
  text "C. SOLDERMASK COLOR;" at 302.463,122.885 h2.16
  text "GREEN" at 350.723,122.885 h2.16
  text "GREEN" at 350.723,122.885 h2.16
  text "BLUE" at 369.773,122.885 h2.16
  text "BLUE" at 369.773,122.885 h2.16
  text "RED" at 391.363,122.885 h2.16
  text "RED" at 391.363,122.885 h2.16
  text "BLACK" at 412.953,122.885 h2.16
  text "BLACK" at 412.953,122.885 h2.16
  text "D. SILKSCREEN COLOR;" at 302.463,117.805 h2.16
  text "D. SILKSCREEN COLOR;" at 302.463,117.805 h2.16
  text "WHITE" at 350.723,117.805 h2.16
  text "WHITE" at 350.723,117.805 h2.16
  text "YELLOW" at 369.773,117.805 h2.16
  text "YELLOW" at 369.773,117.805 h2.16
  text "BLACK" at 391.363,117.805 h2.16
  text "BLACK" at 391.363,117.805 h2.16
  text "E. SURFACE FINISH;" at 302.463,112.725 h2.16
  text "E. SURFACE FINISH;" at 302.463,112.725 h2.16
  text "ENIG" at 350.723,112.725 h2.16
  text "ENIG" at 350.723,112.725 h2.16
  text "IMMERSION SILVER" at 369.773,112.725 h2.16
  text "IMMERSION SILVER" at 369.773,112.725 h2.16
  text "IMMERSION TIN" at 412.953,112.725 h2.16
  text "IMMERSION TIN" at 412.953,112.725 h2.16
  text "HASL" at 350.723,107.645 h2.16
  text "HASL" at 350.723,107.645 h2.16
  text "HASL(PB-FREE)" at 369.773,107.645 h2.16
  text "HASL(PB-FREE)" at 369.773,107.645 h2.16
  text "GOLDEN FINGER" at 412.953,107.645 h2.16
  text "GOLDEN FINGER" at 412.953,107.645 h2.16
  text "F. IMPEDANCE CONTROL;" at 302.463,102.565 h2.16
  text "F. IMPEDANCE CONTROL;" at 302.463,102.565 h2.16
  text "NO" at 350.723,102.565 h2.16
  text "NO" at 350.723,102.565 h2.16
  text "YES" at 369.773,102.565 h2.16
  text "YES" at 369.773,102.565 h2.16
  text "(SEE IMPEDANCE TABLE FOR DETAIL INFORMATION)" at 374.853,102.565 h2.16
  text "(SEE IMPEDANCE TABLE FOR DETAIL INFORMATION)" at 374.853,102.565 h2.16
  text "G. THROUGH VIA;" at 302.463,97.485 h2.16
  text "G. THROUGH VIA;" at 302.463,97.485 h2.16
  text "PLUG THE VIAS WHICH ARE COVERED WITH SOLDERMASK ONE OR TWO SIDE." at 339.293,97.485 h2.16
  text "PLUG THE VIAS WHICH ARE COVERED WITH SOLDERMASK ONE OR TWO SIDE." at 339.293,97.485 h2.16
  text "PLUG MATERIAL:" at 339.293,92.405 h2.16
  text "PLUG MATERIAL:" at 339.293,92.405 h2.16
  text "SOLDERMASK" at 379.933,92.405 h2.16
  text "SOLDERMASK" at 379.933,92.405 h2.16
  text "NON-CONDUCTIVE EPOXY." at 412.953,92.405 h2.16
  text "NON-CONDUCTIVE EPOXY." at 412.953,92.405 h2.16
  text "H. STACK-UP;" at 302.463,87.325 h2.16
  text "H. STACK-UP;" at 302.463,87.325 h2.16
  text "SEE LAYER STACK-UP SEQUENCE FOR OVERALL THICKNESS." at 339.293,87.325 h2.16
  text "SEE LAYER STACK-UP SEQUENCE FOR OVERALL THICKNESS." at 339.293,87.325 h2.16
  text "PCB REQUIREMENTS:" at 302.209,79.705 h2.16
  text "PCB REQUIREMENTS:" at 302.209,79.705 h2.16
  text "1. THIS BOARD WILL CONFORM TO:" at 300.939,74.625 h2.16
  text "1. THIS BOARD WILL CONFORM TO:" at 300.939,74.625 h2.16
  text "IPC-A-600. CURRENT REV., CLASS II" at 300.939,70.815 h2.16
  text "IPC-A-600. CURRENT REV., CLASS II" at 300.939,70.815 h2.16
  text "IPC-6012, CURRENT REV., CLASS II" at 300.939,67.005 h2.16
  text "IPC-6012, CURRENT REV., CLASS II" at 300.939,67.005 h2.16
  text "2. UNLESS OTHERWISE SPECIFIED ALL HOLE DIMENSIONS APPLY AFTER PLATING." at 300.939,61.671 h2.16
  text "2. UNLESS OTHERWISE SPECIFIED ALL HOLE DIMENSIONS APPLY AFTER PLATING." at 300.939,61.671 h2.16
  text "ALL HOLES SHALL BE LOCATED WITHIN .003\" DIAMETER OF TRUE POSITION." at 300.939,57.861 h2.16
  text "ALL HOLES SHALL BE LOCATED WITHIN .003\" DIAMETER OF TRUE POSITION." at 300.939,57.861 h2.16
  text "3. PLATED HOLE WALL THICKNESS SHALL NOT BE LESS THAN .001 INCH MINIMUM" at 300.939,52.781 h2.16
  text "3. PLATED HOLE WALL THICKNESS SHALL NOT BE LESS THAN .001 INCH MINIMUM" at 300.939,52.781 h2.16
  text "B" at -60.655,51.435 h3.3
  text "B" at -60.655,51.435 h3.3
  text "B" at 480.365,51.435 h3.3
  text "B" at 480.365,51.435 h3.3
  text "AVERAGE, WITH NO READING LESS THAN .0008 BY COROSS SECTION." at 305.511,49.225 h2.16
  text "AVERAGE, WITH NO READING LESS THAN .0008 BY COROSS SECTION." at 305.511,49.225 h2.16
  text "4. MATERIAL FR4 RATING 94V-0 MINIMUM EPOXY GLASS LAMINATE." at 300.939,43.891 h2.16
  text "4. MATERIAL FR4 RATING 94V-0 MINIMUM EPOXY GLASS LAMINATE." at 300.939,43.891 h2.16
  text "5. BOARD SHALL BE LPI SOLDER MASKED OVER BARE COPPER BOTH SIDES PER" at 300.939,39.319 h2.16
  text "5. BOARD SHALL BE LPI SOLDER MASKED OVER BARE COPPER BOTH SIDES PER" at 300.939,39.319 h2.16
  text "IPC-SM-840 CLASS II." at 300.939,35.509 h2.16
  text "IPC-SM-840 CLASS II." at 300.939,35.509 h2.16
  text "6. SILKSCREEN SHALL BE PERMANENT NON-CONDUCTIVE INK AND WITH NO OVERLAP" at 300.939,30.429 h2.16
  text "6. SILKSCREEN SHALL BE PERMANENT NON-CONDUCTIVE INK AND WITH NO OVERLAP" at 300.939,30.429 h2.16
  text "ON ANY COMPONENT PAD OR THROUGH HOLE." at 300.939,26.619 h2.16
  text "ON ANY COMPONENT PAD OR THROUGH HOLE." at 300.939,26.619 h2.16
  text "7. MFGR, TO LEGIBLY ETCH OR STAMP/SCREEN WITH PERMANENT NON-CONDUCTIVE INK" at 300.939,21.539 h2.16
  text "7. MFGR, TO LEGIBLY ETCH OR STAMP/SCREEN WITH PERMANENT NON-CONDUCTIVE INK" at 300.939,21.539 h2.16
  text "D. MFGR. LOGO" at 347.929,18.237 h2.16
  text "D. MFGR. LOGO" at 347.929,18.237 h2.16
  text "A. U.L. CODE" at 308.305,17.729 h2.16
  text "A. U.L. CODE" at 308.305,17.729 h2.16
  text ".Legend" at 124.333,16.662 h1.52
  text "E. SUCCESSFUL ELECTRICAL BOARD TEST." at 347.929,14.681 h2.16
  text "E. SUCCESSFUL ELECTRICAL BOARD TEST." at 347.929,14.681 h2.16
  text "B. DATE CODE" at 308.305,14.173 h2.16
  text "B. DATE CODE" at 308.305,14.173 h2.16
  text "C. FLAMMABILITY RATING" at 308.305,10.617 h2.16
  text "C. FLAMMABILITY RATING" at 308.305,10.617 h2.16
  text "8. REMOVE THE FLASHS WHICH SMALLER THAN HOLE SIZE." at 300.939,5.283 h2.16
  text "8. REMOVE THE FLASHS WHICH SMALLER THAN HOLE SIZE." at 300.939,5.283 h2.16
  text "9. REMOVE ALL SHAPE EDGES AND BURRS .005 MAXIMUM." at 300.939,0.203 h2.16
  text "9. REMOVE ALL SHAPE EDGES AND BURRS .005 MAXIMUM." at 300.939,0.203 h2.16
  text "10. PLEASE USE THE SUPPLIED IPC 356 NETLIST TO VERIFY BOARD BEFORE" at 300.939,-5.131 h2.16
  text "10. PLEASE USE THE SUPPLIED IPC 356 NETLIST TO VERIFY BOARD BEFORE" at 300.939,-5.131 h2.16
  text "FABRICATING BOARD." at 300.939,-8.941 h2.16
  text "FABRICATING BOARD." at 300.939,-8.941 h2.16
  text "COMPANY NAME:" at 84.132,-23.597 h1.52
  text "LAYER:" at 43.492,-24.867 h1.91
  text "ST" at 87.942,-27.407 h1.91
  text "ST" at 87.942,-27.407 h1.91
  text "PROJECT NAME:" at 84.132,-31.217 h1.52
  text "DESIGNED BY SOFER" at 11.234,-31.725 h1.52
  text "www.sofer.com.cn" at 11.742,-34.265 h1.52
  text "MB1397" at 86.458,-34.62 h1.91
  text "DESIGNER:" at 44.762,-35.027 h1.52
  text "DESIGNER:" at 44.762,-35.027 h1.52
  text "Shelley" at 57.462,-35.027 h1.52
  text "Shelley" at 57.462,-35.027 h1.52
  text "Tel : +86 21 - 6482 6908" at 6.662,-38.837 h1.52
  text "PROJECT NUMBER:" at 84.132,-38.837 h1.52
  text "REV" at 114.612,-38.837 h1.52
  text "REV" at 114.612,-38.837 h1.52
  text "Mail: design@sofer.com.cn" at 6.662,-41.377 h1.52
  text "DATE:" at 44.762,-41.377 h1.52
  text "2018.07.25" at 52.382,-41.377 h1.52
  text "D031-028A2" at 87.942,-42.647 h1.91
  text "B" at 117.152,-42.647 h1.91
  text "A" at -60.655,-55.245 h3.3
  text "A" at -60.655,-55.245 h3.3
  text "A" at 480.365,-55.245 h3.3
  text "A" at 480.365,-55.245 h3.3
  text "DATA" at 378.358,-62.738 h1.91
  text "UNLESS OTHERWISE SPECIFIED" at 294.767,-62.967 h1.91
  text "SIGNATURES" at 343.713,-63.5 h1.91
  text "COMPANY NAME" at 429.362,-65.938 h2.29
  text "LOGO" at 395.732,-66.116 h2.29
  text "DRAWN" at 343.713,-68.58 h1.91
  text "YY-MM-DD" at 376.072,-69.088 h1.91
  text "DIMENSIONS ARE IN INCHES" at 294.945,-69.672 h1.91
  text "TOLERANCES ON;" at 294.945,-73.838 h1.91
  text "CHECKED" at 343.713,-74.422 h1.91
  text "YY-MM-DD" at 375.691,-74.422 h1.91
  text "TITLE" at 393.725,-76.657 h1.91
  text "2 PL DECIMALS +" at 294.945,-77.826 h1.91
  text "ENGGRG" at 343.84,-79.121 h1.91
  text "YY-MM-DD" at 375.945,-79.248 h1.91
  text "PROJECT NAME  *" at 409.524,-80.061 h2.29
  text "3 PL DECIMALS +" at 295.148,-81.763 h1.91
  text "ISSUED" at 343.713,-84.049 h1.91
  text "ANGLES +" at 294.767,-85.979 h1.91
  text "SIZE   B" at 393.395,-87.757 h1.91
  text "DWG  NO   *******" at 415.925,-87.757 h1.91
  text "REV **" at 462.356,-87.909 h1.91
  text "FRACTIONS +" at 294.767,-89.967 h1.91
  text "SCALE  1:1" at 393.573,-93.65 h1.91
  text "SHEET    1  OF  1" at 442.849,-93.802 h1.91
  text "6" at -9.855,-100.965 h3.3
  text "6" at -9.855,-100.965 h3.3
  text "5" at 79.045,-100.965 h3.3
  text "5" at 79.045,-100.965 h3.3
  text "4" at 167.945,-100.965 h3.3
  text "4" at 167.945,-100.965 h3.3
  text "3" at 256.845,-100.965 h3.3
  text "3" at 256.845,-100.965 h3.3
  text "2" at 345.745,-100.965 h3.3
  text "2" at 345.745,-100.965 h3.3
  text "1" at 434.645,-100.965 h3.3
  text "1" at 434.645,-100.965 h3.3

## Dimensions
7.62,5.715 to 7.62,167.005 on M2-Board Dimensions
5.105,172.72 to 5.156,0 on M2-Board Dimensions
31.285,149.811 to 99.865,149.811 on M2-Board Dimensions
7.62,167.005 to 110.49,167.005 on M2-Board Dimensions
-0.064,167.564 to 118.11,167.462 on M2-Board Dimensions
